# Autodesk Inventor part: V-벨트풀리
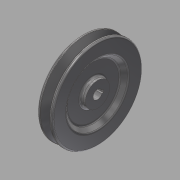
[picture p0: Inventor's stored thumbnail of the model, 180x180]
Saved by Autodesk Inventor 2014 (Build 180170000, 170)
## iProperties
Created: 2015-12
Part Number: V-벨트풀리
Document SubType Name: Modeling
Designer: mdu
Density: 7.87 g/cm^3
Material: 스테인레스 스틸
Appearance: 반연마
Mass: 1106 g
Surface Area: 369.462 cm^2
Volume: 140.533 cm^3
Author: mdu
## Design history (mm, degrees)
sketch "스케치1"
  geometry: L1 (-10, 0)-(10, 0); L2 (-10, 0)-(-10, 16); L3 (-10, 16)-(-4, 16); L4 (-4, 16)-(-4, 35); L5 (-4, 35)-(-10, 41); L6 (-10, 41)-(-10, 59.5); L7 (-10, 59.5)-(-6.062, 59.5); L8 (-6.062, 59.5)-(-2.001, 47); L9 (-2.001, 47)-(2.001, 47); L10 (2.001, 47)-(6.062, 59.5); L11 (6.062, 59.5)-(10, 59.5); L12 (10, 59.5)-(10, 41); L13 (10, 41)-(4, 35); L14 (4, 35)-(4, 16); L15 (4, 16)-(10, 16); L16 (10, 16)-(10, 0); L17 (-4.6, 55)-(4.6, 55); 2 further points
  constraints: 34 end point, 7 parallel, 6 equal length, 5 collinear, 3 perpendicular, 2 point on line, 1 coincident, 1 horizontal, 1 midpoint
  dimensions: "d0" = 20 distance of L1.start L1.end; "d1" = 9.2 distance of L17.start L17.end; "d2" = 36 deg angle of L10 L8; "d3" = 4.5 distance between parallel lines of L7 L17; "d4" = 8 distance between parallel lines of L9 L17; "d6" = 110 diameter of L17 L1; "d7" = 32 diameter of L3 L1; "d8" = 82 diameter of L5.end L1; "d9" = 6 distance of L2.end L3.end; "d10" = 135 deg angle of L4 L5
revolve "회전1" sketch "스케치1" stored, may be unused: angle "d11" = 90 deg
fillet "모깎기1" dims "d12" = 2, "d13" = 0.5, "d14" = 1, "d15" = 3
sketch "스케치2"
  geometry: L1 (-2, 5.657)-(-2, 7.8); L2 (-2, 7.8)-(2, 7.8); L3 (2, 7.8)-(2, 5.657); A1 r 6 centre (0, 0) between (-2, 5.657) and (2, 5.657); 1 further point
  constraints: 6 end point, 2 parallel, 2 point on circle, 1 centre point, 1 coincident, 1 perpendicular, 1 vertical
  dimensions: "d16" = 12 diameter of A1; "d17" = 4 distance of L1.end L2.end; "d18" = 13.8 dimension on A1 L2 (computed from d16)
extrude "돌출1" cut sketch "스케치2" stored distance "d19" = 10; taper "d20" = 0 deg
node "솔리드1"
